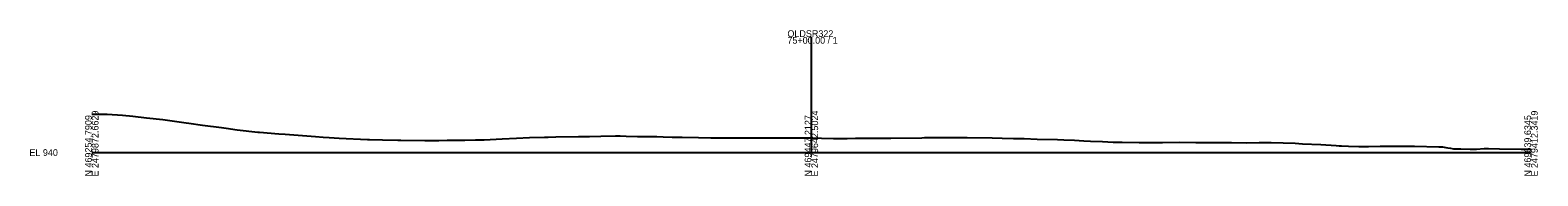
# Model space of a CAD drawing. Extents: x -26 to 2480020, y -10 to 469659.
# Drawn here: x -26 to 603, y 5490 to 5551 of the extents above; entities that cross this region are included whole.
import ezdxf

# ---------------------------------------------------------------- set-up
doc = ezdxf.new("R2010")
doc.units = 0
doc.layers.add('DESIGN - SHEET - Light Grid', color=7, linetype='Continuous')
doc.layers.add('SURVEY - GROUND - Top of Ground', color=7, linetype='Continuous')

msp = doc.modelspace()

# ---------------------------------------------------------------- linework, layer by layer
at = {"layer": 'DESIGN - SHEET - Light Grid'}
for p, q in [((300, 5500), (300, 5548.15)), ((0, 5500), (300, 5500)), ((300, 5500), (600, 5500))]:
    msp.add_line(p, q, dxfattribs=at)
at = {"layer": 'SURVEY - GROUND - Top of Ground'}
msp.add_lwpolyline([(0, 5516), (5.5, 5516.01), (6.43, 5516.05), (12.83, 5515.53), (17.07, 5515.13), (22.8, 5514.51), (29.56, 5513.75), (37.47, 5512.67), (39.37, 5512.39), (40.39, 5512.25), (46.12, 5511.47), (54.05, 5510.39), (55.99, 5510.12), (60.65, 5509.49), (69.24, 5508.52), (69.56, 5508.49), (69.98, 5508.46), (78.03, 5507.81), (80.57, 5507.64), (93.33, 5506.72), (96.48, 5506.48), (98.93, 5506.3), (103.15, 5506.01), (115, 5505.47), (115.45, 5505.46), (115.84, 5505.44), (121.17, 5505.31), (127.58, 5505.16), (127.98, 5505.16), (128.79, 5505.14), (138.87, 5504.99), (144.63, 5505.06), (148.2, 5505.13), (153.29, 5505.16), (155.52, 5505.18), (159.96, 5505.25), (162, 5505.3), (163.54, 5505.37), (171.14, 5505.7), (177.12, 5505.94), (182.42, 5506.21), (188.67, 5506.4), (189.52, 5506.42), (190.2, 5506.43), (193.39, 5506.49), (202.88, 5506.69), (207.53, 5506.74), (212.25, 5506.83), (218.3, 5506.91), (220.26, 5506.92), (222.81, 5506.86), (227.55, 5506.74), (231.86, 5506.7), (235.5, 5506.65), (238.23, 5506.57), (241.95, 5506.48), (246.11, 5506.42), (252.91, 5506.28), (258.1, 5506.19), (268.2, 5506.2), (268.78, 5506.2), (269.3, 5506.2), (281.56, 5506.19), (282.2, 5506.18), (282.69, 5506.18), (290.33, 5506.15), (297.18, 5506.15), (297.7, 5506.14), (298.16, 5506.13), (300, 5506.08), (304.21, 5505.97), (309.25, 5505.89), (312.48, 5505.91), (314.88, 5505.92), (318.43, 5505.97), (322.42, 5505.98), (326.08, 5506.02), (329.05, 5506.01), (331.97, 5506.03), (333.09, 5506.03), (345.98, 5506.2), (347.19, 5506.22), (348.38, 5506.25), (355.01, 5506.32), (361.45, 5506.33), (362.32, 5506.32), (364.9, 5506.28), (375.38, 5506.1), (379.55, 5506), (384.3, 5505.91), (388.67, 5505.84), (394.17, 5505.64), (402.59, 5505.39), (405.2, 5505.3), (409.74, 5505.11), (413.56, 5504.93), (416.29, 5504.8), (421.32, 5504.57), (425.83, 5504.36), (429.49, 5504.27), (436.7, 5504.21), (440.79, 5504.19), (446.36, 5504.21), (453.43, 5504.28), (460.31, 5504.21), (465.52, 5504.17), (468.42, 5504.15), (471.3, 5504.13), (475.09, 5504.21), (481.29, 5504.12), (486.71, 5504.14), (491.61, 5504.14), (501.67, 5503.89), (503.13, 5503.73), (504.73, 5503.64), (512.34, 5503.3), (518.7, 5502.93), (520.03, 5502.85), (520.98, 5502.79), (523.96, 5502.69), (528.25, 5502.55), (531.21, 5502.51), (531.61, 5502.56), (532.29, 5502.59), (537.05, 5502.67), (551.46, 5502.69), (561.59, 5502.43), (561.92, 5502.41), (563.07, 5502.32), (564.42, 5502.1), (565.25, 5501.98), (566.46, 5501.82), (567.73, 5501.52), (568.18, 5501.5), (570.78, 5501.49), (574.6, 5501.44), (577.23, 5501.47), (580.42, 5501.72), (581.03, 5501.72), (582.24, 5501.69), (586.79, 5501.5), (595.89, 5501.47), (597.74, 5501.47), (599.62, 5501.46), (600, 5501.43)], dxfattribs=at)

# ---------------------------------------------------------------- texts
at = {"layer": 'DESIGN - SHEET - Light Grid'}
for s, p in [('OLDSR322', (290, 5548.15)), ('75+00.00 / 1', (290, 5545.35)), ('EL 940', (-26, 5498.6))]:
    msp.add_text(s, height=2.8, dxfattribs=at).set_placement(p)
for s, p in [('N 469254.7909', (0, 5490)), ('E 2479872.6629', (2.8, 5490)), ('N 469447.2127', (300, 5490)), ('E 2479642.5024', (302.8, 5490)), ('N 469639.6345', (600, 5490)), ('E 2479412.3419', (602.8, 5490))]:
    msp.add_text(s, height=2.8, rotation=90, dxfattribs=at).set_placement(p)

doc.saveas('drawing.dxf')
